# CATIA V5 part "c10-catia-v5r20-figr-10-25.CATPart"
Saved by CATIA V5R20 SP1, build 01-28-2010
Part number: Part1
Bounding box of the stored display mesh (mm): x -65.919 to 25.581, y -200.404 to 0.194, z 0 to 71.635
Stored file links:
  D:\v5_r20\psrt_files_downloaded\c10\c10-catia-v5r20-figr-10-25.CATPart
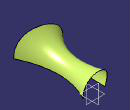
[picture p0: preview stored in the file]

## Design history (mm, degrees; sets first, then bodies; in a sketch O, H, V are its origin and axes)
Set1
  Sketch1 on xy-plane, origin (0, 0, 0), H (1, 0, 0), V (0, 1, 0)
    spline S1 through (-36.6295, 0) (-39.5961, -76.7629) (-56.6868, -154.7631) (-92.5015, -194.2587)
    point P1 (-36.6295, 0)
    coincidence: P1 H
  Sketch2 on xy-plane, origin (0, 0, 0), H (1, 0, 0), V (0, 1, 0)
    spline S1 through (25.5807, 0) (5.5021, -50.6307) (25.5807, -200.404)
    point P1 (25.5807, 0)
    coincidence: P1 H
  Sketch3 on zx-plane, origin (0, 0, 0), H (-1, 0, 0), V (0, 0, 1)
    spline S1 through (-25.5807, 0) (16.4189, 47.2175) (28.9802, 46.33) (36.6295, 0)
    reference projected point E1 (36.6295, 0) from vertex of Sketch1
    reference projected point E2 (-25.5807, 0) from vertex of Sketch2
    point P1 (-25.5807, 0)
    point P2 (36.6295, 0)
    coincidence: P1 H, P2 H, E1 P2, P1 E2
  Sweep1: type Unspec, Profile Sketch3, Guide (Sketch1; Sketch2), FittingPoints (vertex of Sketch1; vertex of Sketch2)
Body1 (main body)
